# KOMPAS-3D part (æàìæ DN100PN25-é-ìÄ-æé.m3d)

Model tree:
1. Объединить компоненты:1  (labels: СЕНС DN100PN25-В-НО)
2. Эскиз:1
3. Операция выдавливания:1
     Расстояние 1 = 14
4. Фаска:1
     Угол = 45; Длина 1 = 2; Длина 2 = 2

Referenced files in D:\Савин\!СЕНСОР\3D для заказчика\!Новый перечень\СЕНС\6. СЕНС-В-НО\DN100\: СЕНС DN100PN25-В-НО.a3d
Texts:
  СЕНС DN100PN25-В-НО-СВ
  ООО НПП Сенсор
  СЕНС DN100PN25-В-НО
